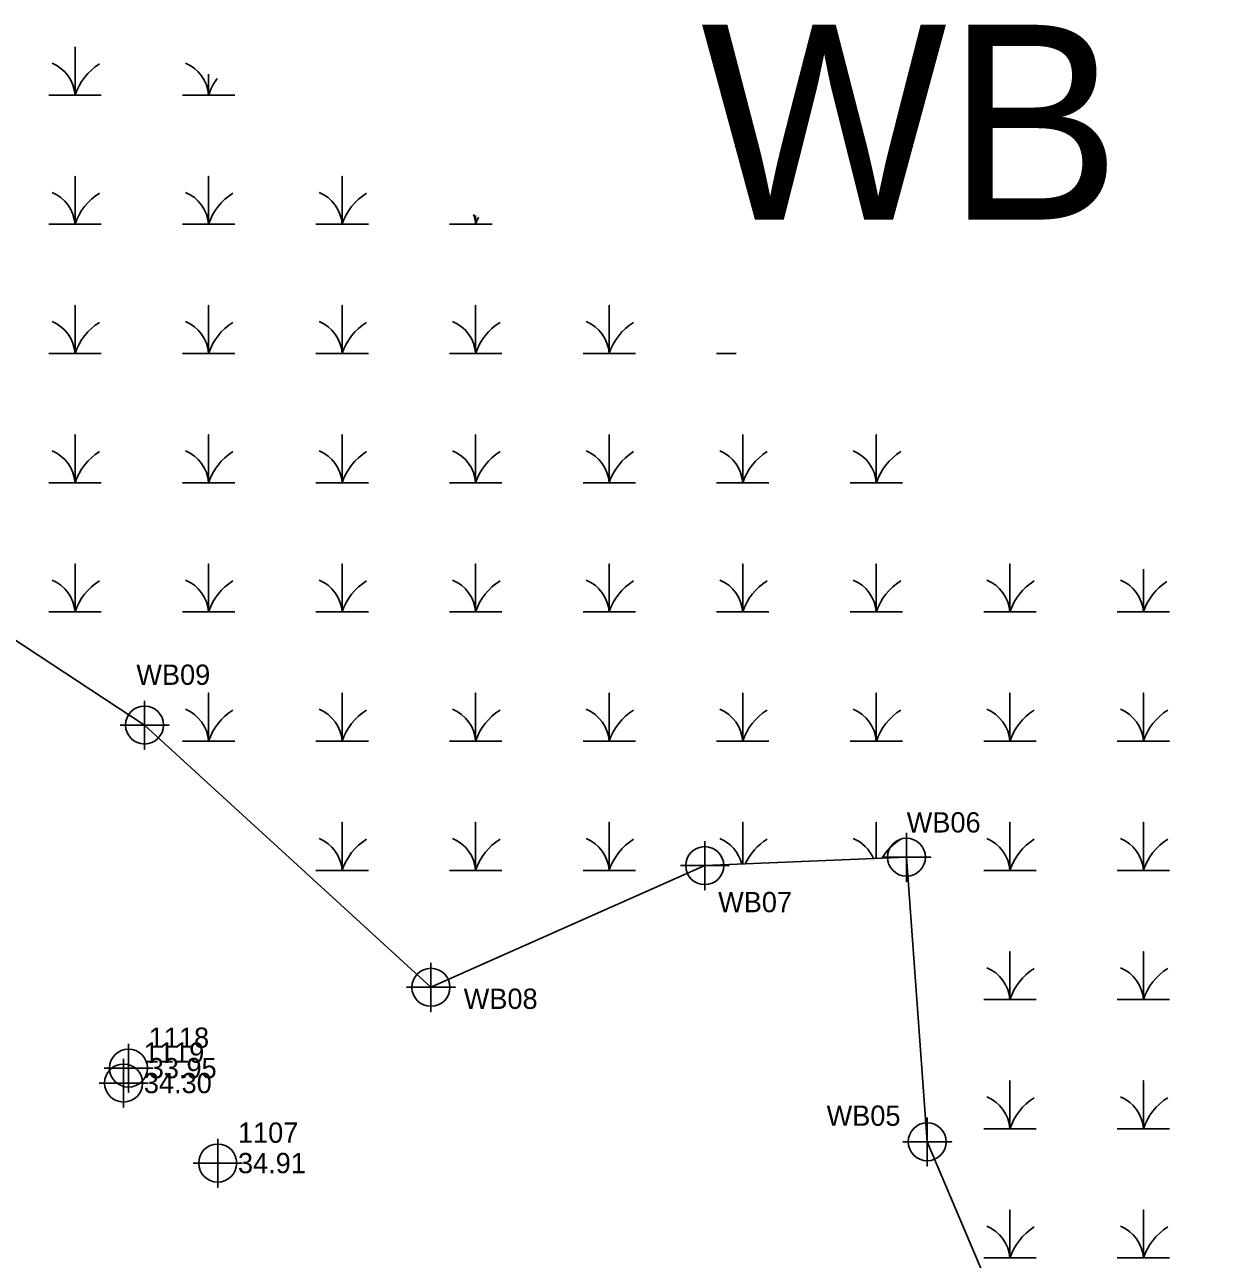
# Model space of a CAD drawing. Extents: x 2138832 to 2141061, y 149156 to 150675.
# Drawn here: x 2140366.3 to 2140515.2, y 149528.1 to 149680.2 of the extents above; entities that cross this region are included whole.
import ezdxf

# ---------------------------------------------------------------- set-up
doc = ezdxf.new("R2010")
doc.units = 0
for name, color, linetype in [('Default', 7, 'Continuous'), ('Exist Environmental Wetland Boundary', 7, 'Continuous'), ('Exist Environmental Wetland Boundary Cogo Number', 7, 'Continuous'), ('Exist Environmental Wetland Boundary Cogo Point CELL', 7, 'Continuous'), ('Exist Roads EOP Cogo Elevation', 7, 'Continuous'), ('Exist Roads EOP Cogo Number', 7, 'Continuous'), ('Exist Roads EOP Cogo Point CELL', 7, 'Continuous'), ('Exist Utilities Telephone UG FO SUE LOS C Cogo Elevation', 7, 'Continuous'), ('Exist Utilities Telephone UG FO SUE LOS C Cogo Number', 7, 'Continuous'), ('Exist Utilities Telephone UG FO SUE LOS C Cogo Point CELL', 7, 'Continuous')]:
    doc.layers.add(name, color=color, linetype=linetype)

msp = doc.modelspace()

# ---------------------------------------------------------------- linework, layer by layer
at = {"layer": 'Exist Environmental Wetland Boundary'}
msp.add_lwpolyline([(2140220.74, 149663.51), (2140255.42, 149635.3), (2140277.39, 149631.77), (2140314.58, 149625.36), (2140349.86, 149614.36), (2140381.04, 149593.89), (2140416.32, 149561.58), (2140450.05, 149576.57), (2140474.9, 149577.61), (2140477.45, 149542.55), (2140488.03, 149517.58), (2140501.09, 149504.55), (2140539.61, 149485.41), (2140594.36, 149464.34)], dxfattribs=at)
at = {"layer": 'Exist Environmental Wetland Boundary Cogo Point CELL'}
msp.add_line((2140451.51, 149639.66), (2140453.93, 149639.66), dxfattribs=at)
for points in [[(2140369.25, 149671.5), (2140372.48, 149671.5), (2140372.48, 149677.41), (2140372.48, 149671.5), (2140375.7, 149671.5)], [(2140385.7, 149671.5), (2140388.93, 149671.5), (2140388.93, 149674.08)], [(2140388.93, 149674.08), (2140388.93, 149671.5), (2140392.15, 149671.5)], [(2140369.25, 149655.58), (2140372.48, 149655.58), (2140372.48, 149661.5), (2140372.48, 149655.58), (2140375.7, 149655.58)], [(2140385.7, 149655.58), (2140388.93, 149655.58), (2140388.93, 149661.5), (2140388.93, 149655.58), (2140392.15, 149655.58)], [(2140402.15, 149655.58), (2140405.38, 149655.58), (2140405.38, 149661.5), (2140405.38, 149655.58), (2140408.61, 149655.58)], [(2140418.61, 149655.58), (2140421.83, 149655.58), (2140421.83, 149656.66)], [(2140421.83, 149656.66), (2140421.83, 149655.58), (2140423.87, 149655.58)], [(2140369.25, 149639.66), (2140372.48, 149639.66), (2140372.48, 149645.58), (2140372.48, 149639.66), (2140375.7, 149639.66)], [(2140385.7, 149639.66), (2140388.93, 149639.66), (2140388.93, 149645.58), (2140388.93, 149639.66), (2140392.15, 149639.66)], [(2140402.15, 149639.66), (2140405.38, 149639.66), (2140405.38, 149645.58), (2140405.38, 149639.66), (2140408.61, 149639.66)], [(2140418.61, 149639.66), (2140421.83, 149639.66), (2140421.83, 149645.58), (2140421.83, 149639.66), (2140425.06, 149639.66)], [(2140435.06, 149639.66), (2140438.28, 149639.66), (2140438.28, 149645.58), (2140438.28, 149639.66), (2140441.51, 149639.66)], [(2140369.25, 149623.74), (2140372.48, 149623.74), (2140372.48, 149629.66), (2140372.48, 149623.74), (2140375.7, 149623.74)], [(2140385.7, 149623.74), (2140388.93, 149623.74), (2140388.93, 149629.66), (2140388.93, 149623.74), (2140392.15, 149623.74)], [(2140402.15, 149623.74), (2140405.38, 149623.74), (2140405.38, 149629.66), (2140405.38, 149623.74), (2140408.61, 149623.74)], [(2140418.61, 149623.74), (2140421.83, 149623.74), (2140421.83, 149629.66), (2140421.83, 149623.74), (2140425.06, 149623.74)], [(2140435.06, 149623.74), (2140438.28, 149623.74), (2140438.28, 149629.66), (2140438.28, 149623.74), (2140441.51, 149623.74)], [(2140451.51, 149623.74), (2140454.73, 149623.74), (2140454.73, 149629.66), (2140454.73, 149623.74), (2140457.96, 149623.74)], [(2140467.96, 149623.74), (2140471.18, 149623.74), (2140471.18, 149629.66), (2140471.18, 149623.74), (2140474.41, 149623.74)], [(2140369.25, 149607.82), (2140372.48, 149607.82), (2140372.48, 149613.74), (2140372.48, 149607.82), (2140375.7, 149607.82)], [(2140385.7, 149607.82), (2140388.93, 149607.82), (2140388.93, 149613.74), (2140388.93, 149607.82), (2140392.15, 149607.82)], [(2140402.15, 149607.82), (2140405.38, 149607.82), (2140405.38, 149613.74), (2140405.38, 149607.82), (2140408.61, 149607.82)], [(2140418.61, 149607.82), (2140421.83, 149607.82), (2140421.83, 149613.74), (2140421.83, 149607.82), (2140425.06, 149607.82)], [(2140435.06, 149607.82), (2140438.28, 149607.82), (2140438.28, 149613.74), (2140438.28, 149607.82), (2140441.51, 149607.82)], [(2140451.51, 149607.82), (2140454.73, 149607.82), (2140454.73, 149613.74), (2140454.73, 149607.82), (2140457.96, 149607.82)], [(2140467.96, 149607.82), (2140471.18, 149607.82), (2140471.18, 149613.74), (2140471.18, 149607.82), (2140474.41, 149607.82)], [(2140484.41, 149607.82), (2140487.64, 149607.82), (2140487.64, 149613.74), (2140487.64, 149607.82), (2140490.86, 149607.82)], [(2140500.86, 149607.82), (2140504.09, 149607.82), (2140504.09, 149613.1)], [(2140504.09, 149613.1), (2140504.09, 149607.82), (2140507.31, 149607.82)], [(2140381.04, 149596.89), (2140381.04, 149590.89), (2140381.04, 149593.89), (2140384.04, 149593.89), (2140378.04, 149593.89)], [(2140385.7, 149591.91), (2140388.93, 149591.91), (2140388.93, 149597.82), (2140388.93, 149591.91), (2140392.15, 149591.91)], [(2140402.15, 149591.91), (2140405.38, 149591.91), (2140405.38, 149597.82), (2140405.38, 149591.91), (2140408.61, 149591.91)], [(2140418.61, 149591.91), (2140421.83, 149591.91), (2140421.83, 149597.82), (2140421.83, 149591.91), (2140425.06, 149591.91)], [(2140435.06, 149591.91), (2140438.28, 149591.91), (2140438.28, 149597.82), (2140438.28, 149591.91), (2140441.51, 149591.91)], [(2140451.51, 149591.91), (2140454.73, 149591.91), (2140454.73, 149597.82), (2140454.73, 149591.91), (2140457.96, 149591.91)], [(2140467.96, 149591.91), (2140471.18, 149591.91), (2140471.18, 149597.82), (2140471.18, 149591.91), (2140474.41, 149591.91)], [(2140484.41, 149591.91), (2140487.64, 149591.91), (2140487.64, 149597.82), (2140487.64, 149591.91), (2140490.86, 149591.91)], [(2140500.86, 149591.91), (2140504.09, 149591.91), (2140504.09, 149597.82), (2140504.09, 149591.91), (2140507.31, 149591.91)], [(2140402.15, 149575.99), (2140405.38, 149575.99), (2140405.38, 149581.91), (2140405.38, 149575.99), (2140408.61, 149575.99)], [(2140418.61, 149575.99), (2140421.83, 149575.99), (2140421.83, 149581.91), (2140421.83, 149575.99), (2140425.06, 149575.99)], [(2140435.06, 149575.99), (2140438.28, 149575.99), (2140438.28, 149581.91), (2140438.28, 149575.99), (2140441.51, 149575.99)], [(2140454.73, 149576.77), (2140454.73, 149581.91), (2140454.73, 149576.77)], [(2140471.18, 149577.46), (2140471.18, 149581.91), (2140471.18, 149577.46)], [(2140484.41, 149575.99), (2140487.64, 149575.99), (2140487.64, 149581.91), (2140487.64, 149575.99), (2140490.86, 149575.99)], [(2140500.86, 149575.99), (2140504.09, 149575.99), (2140504.09, 149581.91), (2140504.09, 149575.99), (2140507.31, 149575.99)], [(2140474.9, 149580.61), (2140474.9, 149574.61), (2140474.9, 149577.61), (2140477.9, 149577.61), (2140471.9, 149577.61)], [(2140450.05, 149579.57), (2140450.05, 149573.57), (2140450.05, 149576.57), (2140453.05, 149576.57), (2140447.05, 149576.57)], [(2140484.41, 149560.07), (2140487.64, 149560.07), (2140487.64, 149565.99), (2140487.64, 149560.07), (2140490.86, 149560.07)], [(2140500.86, 149560.07), (2140504.09, 149560.07), (2140504.09, 149565.99), (2140504.09, 149560.07), (2140507.31, 149560.07)], [(2140416.32, 149564.58), (2140416.32, 149558.58), (2140416.32, 149561.58), (2140419.32, 149561.58), (2140413.32, 149561.58)], [(2140484.41, 149544.15), (2140487.64, 149544.15), (2140487.64, 149550.07), (2140487.64, 149544.15), (2140490.86, 149544.15)], [(2140500.86, 149544.15), (2140504.09, 149544.15), (2140504.09, 149550.07), (2140504.09, 149544.15), (2140507.31, 149544.15)], [(2140477.45, 149545.55), (2140477.45, 149539.55), (2140477.45, 149542.55), (2140480.45, 149542.55), (2140474.45, 149542.55)], [(2140484.41, 149528.24), (2140487.64, 149528.24), (2140487.64, 149534.15), (2140487.64, 149528.24), (2140490.86, 149528.24)], [(2140500.86, 149528.24), (2140504.09, 149528.24), (2140504.09, 149534.15), (2140504.09, 149528.24), (2140507.31, 149528.24)]]:
    msp.add_lwpolyline(points, dxfattribs=at)
for centre in [(2140381.04, 149593.89), (2140450.05, 149576.57), (2140474.9, 149577.61), (2140416.32, 149561.58), (2140477.45, 149542.55)]:
    msp.add_circle(centre, 2.34, dxfattribs=at)
for centre, radius, start, end in [((2140367.88, 149671.16), 4.61, 4.1403, 67.535), ((2140379.32, 149669.22), 7.21, 122.1274, 161.6222), ((2140384.33, 149671.16), 4.61, 4.1403, 67.535), ((2140395.77, 149669.22), 7.21, 143.3949, 161.6222), ((2140367.88, 149655.25), 4.61, 4.1403, 67.535), ((2140379.32, 149653.31), 7.21, 122.1274, 161.6222), ((2140384.33, 149655.25), 4.61, 4.1403, 67.535), ((2140395.77, 149653.31), 7.21, 122.1274, 161.6222), ((2140400.78, 149655.25), 4.61, 4.1403, 67.535), ((2140412.22, 149653.31), 7.21, 122.1274, 161.6222), ((2140417.23, 149655.25), 4.61, 4.1403, 19.6156), ((2140428.67, 149653.31), 7.21, 153.9928, 161.6222), ((2140367.88, 149639.33), 4.61, 4.1403, 67.535), ((2140379.32, 149637.39), 7.21, 122.1274, 161.6222), ((2140384.33, 149639.33), 4.61, 4.1403, 67.535), ((2140395.77, 149637.39), 7.21, 122.1274, 161.6222), ((2140400.78, 149639.33), 4.61, 4.1403, 67.535), ((2140412.22, 149637.39), 7.21, 122.1274, 161.6222), ((2140417.23, 149639.33), 4.61, 4.1403, 67.535), ((2140428.67, 149637.39), 7.21, 122.1274, 161.6222), ((2140433.68, 149639.33), 4.61, 4.1403, 67.535), ((2140445.12, 149637.39), 7.21, 122.1274, 161.6222), ((2140367.88, 149623.41), 4.61, 4.1403, 67.535), ((2140379.32, 149621.47), 7.21, 122.1274, 161.6222), ((2140384.33, 149623.41), 4.61, 4.1403, 67.535), ((2140395.77, 149621.47), 7.21, 122.1274, 161.6222), ((2140400.78, 149623.41), 4.61, 4.1403, 67.535), ((2140412.22, 149621.47), 7.21, 122.1274, 161.6222), ((2140417.23, 149623.41), 4.61, 4.1403, 67.535), ((2140428.67, 149621.47), 7.21, 122.1274, 161.6222), ((2140433.68, 149623.41), 4.61, 4.1403, 67.535), ((2140445.12, 149621.47), 7.21, 122.1274, 161.6222), ((2140450.13, 149623.41), 4.61, 4.1403, 67.535), ((2140461.57, 149621.47), 7.21, 122.1274, 161.6222), ((2140466.58, 149623.41), 4.61, 4.1403, 67.535), ((2140478.03, 149621.47), 7.21, 122.1274, 161.6222), ((2140367.88, 149607.49), 4.61, 4.1403, 67.535), ((2140379.32, 149605.55), 7.21, 122.1274, 161.6222), ((2140384.33, 149607.49), 4.61, 4.1403, 67.535), ((2140395.77, 149605.55), 7.21, 122.1274, 161.6222), ((2140400.78, 149607.49), 4.61, 4.1403, 67.535), ((2140412.22, 149605.55), 7.21, 122.1274, 161.6222), ((2140417.23, 149607.49), 4.61, 4.1403, 67.535), ((2140428.67, 149605.55), 7.21, 122.1274, 161.6222), ((2140433.68, 149607.49), 4.61, 4.1403, 67.535), ((2140445.12, 149605.55), 7.21, 122.1274, 161.6222), ((2140450.13, 149607.49), 4.61, 4.1403, 67.535), ((2140461.57, 149605.55), 7.21, 122.1274, 161.6222), ((2140466.58, 149607.49), 4.61, 4.1403, 67.535), ((2140478.03, 149605.55), 7.21, 122.1274, 161.6222), ((2140483.04, 149607.49), 4.61, 4.1403, 67.535), ((2140494.48, 149605.55), 7.21, 122.1274, 161.6222), ((2140499.49, 149607.49), 4.61, 4.1403, 67.535), ((2140510.93, 149605.55), 7.21, 123.2986, 161.6222), ((2140384.33, 149591.57), 4.61, 4.1403, 67.535), ((2140395.77, 149589.63), 7.21, 122.1274, 161.6222), ((2140400.78, 149591.57), 4.61, 4.1403, 67.535), ((2140412.22, 149589.63), 7.21, 122.1274, 161.6222), ((2140417.23, 149591.57), 4.61, 4.1403, 67.535), ((2140428.67, 149589.63), 7.21, 122.1274, 161.6222), ((2140433.68, 149591.57), 4.61, 4.1403, 67.535), ((2140445.12, 149589.63), 7.21, 122.1274, 161.6222), ((2140450.13, 149591.57), 4.61, 4.1403, 67.535), ((2140461.57, 149589.63), 7.21, 122.1274, 161.6222), ((2140466.58, 149591.57), 4.61, 4.1403, 67.535), ((2140478.03, 149589.63), 7.21, 122.1274, 161.6222), ((2140483.04, 149591.57), 4.61, 4.1403, 67.535), ((2140494.48, 149589.63), 7.21, 122.1274, 161.6222), ((2140499.49, 149591.57), 4.61, 4.1403, 67.535), ((2140510.93, 149589.63), 7.21, 122.1274, 161.6222), ((2140400.78, 149575.66), 4.61, 4.1403, 67.535), ((2140412.22, 149573.72), 7.21, 122.1274, 161.6222), ((2140417.23, 149575.66), 4.61, 4.1403, 67.535), ((2140428.67, 149573.72), 7.21, 122.1274, 161.6222), ((2140433.68, 149575.66), 4.61, 4.1403, 67.535), ((2140445.12, 149573.72), 7.21, 122.1274, 161.6222), ((2140450.13, 149575.66), 4.61, 13.875, 67.535), ((2140461.57, 149573.72), 7.21, 122.1274, 154.8451), ((2140466.58, 149575.66), 4.61, 22.7975, 67.535), ((2140478.03, 149573.72), 7.21, 122.1274, 148.461), ((2140483.04, 149575.66), 4.61, 4.1403, 67.535), ((2140494.48, 149573.72), 7.21, 122.1274, 161.6222), ((2140499.49, 149575.66), 4.61, 4.1403, 67.535), ((2140510.93, 149573.72), 7.21, 122.1274, 161.6222), ((2140483.04, 149559.74), 4.61, 4.1403, 67.535), ((2140494.48, 149557.8), 7.21, 122.1274, 161.6222), ((2140499.49, 149559.74), 4.61, 4.1403, 67.535), ((2140510.93, 149557.8), 7.21, 122.1274, 161.6222), ((2140483.04, 149543.82), 4.61, 4.1403, 67.535), ((2140494.48, 149541.88), 7.21, 122.1274, 161.6222), ((2140499.49, 149543.82), 4.61, 4.1403, 67.535), ((2140510.93, 149541.88), 7.21, 122.1274, 161.6222), ((2140483.04, 149527.9), 4.61, 4.1403, 67.535), ((2140494.48, 149525.96), 7.21, 122.1274, 161.6222), ((2140499.49, 149527.9), 4.61, 4.1403, 67.535), ((2140510.93, 149525.96), 7.21, 122.1274, 161.6222)]:
    msp.add_arc(centre, radius, start, end, dxfattribs=at)
at = {"layer": 'Exist Roads EOP Cogo Point CELL'}
msp.add_lwpolyline([(2140390.05, 149542.93), (2140390.05, 149536.93), (2140390.05, 149539.93), (2140393.05, 149539.93), (2140387.05, 149539.93)], dxfattribs=at)
msp.add_circle((2140390.05, 149539.93), 2.34, dxfattribs=at)
at = {"layer": 'Exist Utilities Telephone UG FO SUE LOS C Cogo Point CELL'}
for points in [[(2140379.06, 149554.63), (2140379.06, 149548.63), (2140379.06, 149551.63), (2140382.06, 149551.63), (2140376.06, 149551.63)], [(2140378.46, 149552.79), (2140378.46, 149546.79), (2140378.46, 149549.79), (2140381.46, 149549.79), (2140375.46, 149549.79)]]:
    msp.add_lwpolyline(points, dxfattribs=at)
for centre in [(2140379.06, 149551.63), (2140378.46, 149549.79)]:
    msp.add_circle(centre, 2.34, dxfattribs=at)

# ---------------------------------------------------------------- texts
at = {"layer": 'Default'}
msp.add_text('WB', height=24, dxfattribs=at).set_placement((2140449.58, 149656.16))
at = {"layer": 'Exist Environmental Wetland Boundary Cogo Number'}
for s, p in [('WB09', (2140380.03, 149598.84)), ('WB06', (2140474.93, 149580.65)), ('WB07', (2140451.7, 149570.83)), ('WB08', (2140420.36, 149558.92)), ('WB05', (2140465.06, 149544.52))]:
    msp.add_text(s, height=2.5, dxfattribs=at).set_placement(p)
at = {"layer": 'Exist Roads EOP Cogo Elevation'}
msp.add_text('34.91', height=2.5, dxfattribs=at).set_placement((2140392.55, 149538.68))
at = {"layer": 'Exist Roads EOP Cogo Number'}
msp.add_text('1107', height=2.5, dxfattribs=at).set_placement((2140392.55, 149542.43))
at = {"layer": 'Exist Utilities Telephone UG FO SUE LOS C Cogo Elevation'}
for s, p in [('33.95', (2140381.56, 149550.38)), ('34.30', (2140380.96, 149548.54))]:
    msp.add_text(s, height=2.5, dxfattribs=at).set_placement(p)
at = {"layer": 'Exist Utilities Telephone UG FO SUE LOS C Cogo Number'}
for s, p in [('1118', (2140381.56, 149554.13)), ('1119', (2140380.96, 149552.29))]:
    msp.add_text(s, height=2.5, dxfattribs=at).set_placement(p)

doc.saveas('drawing.dxf')
